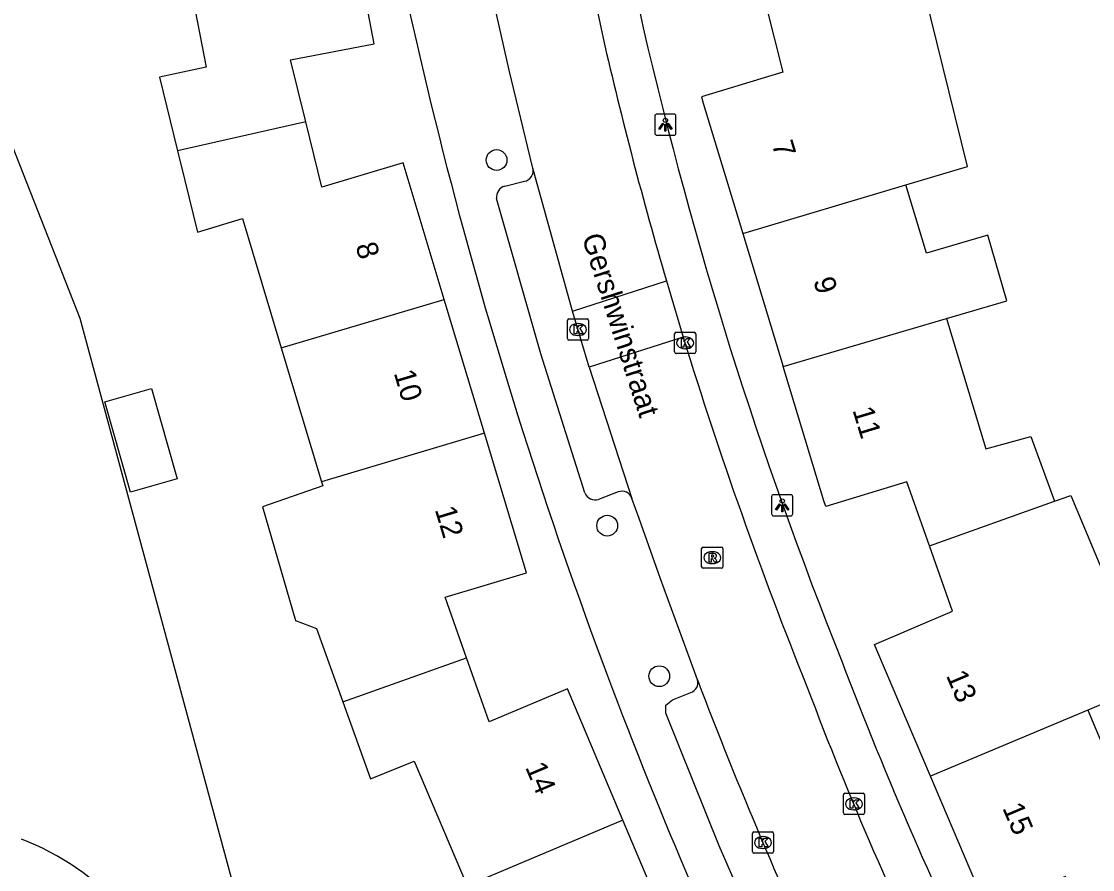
# Model space of a CAD drawing. Extents: x 159053 to 160041, y 380450 to 381422.
# Drawn here: x 159396.6 to 159447, y 380903.9 to 380943.9 of the extents above; entities that cross this region are included whole.
import ezdxf

# ---------------------------------------------------------------- set-up
doc = ezdxf.new("R2010")
doc.units = 0
for name, color, linetype in [('IMGEO_Boom', 7, 'Continuous'), ('IMGEO_Groenvoorziening', 7, 'Continuous'), ('IMGEO_Kolk', 7, 'Continuous'), ('IMGEO_Lichtpunt', 7, 'Continuous'), ('IMGEO_Openbare_ruimte_label', 7, 'Continuous'), ('IMGEO_Pand', 7, 'Continuous'), ('IMGEO_Pand_nummerreeks', 7, 'Continuous'), ('IMGEO_Rijbaan_lokaal_open', 7, 'Continuous'), ('IMGEO_Rioolput', 7, 'Continuous'), ('IMGEO_Voetpad_gesloten', 7, 'Continuous'), ('IMGEO_Voetpad_open', 7, 'Continuous')]:
    doc.layers.add(name, color=color, linetype=linetype)

msp = doc.modelspace()

# ---------------------------------------------------------------- linework, layer by layer
at = {"layer": 'IMGEO_Boom'}
for centre in [(159418.941, 380937.333), (159424.152, 380920.106), (159426.603, 380913.013)]:
    msp.add_circle(centre, 0.489, dxfattribs=at)
at = {"layer": 'IMGEO_Groenvoorziening'}
msp.add_lwpolyline([(159387.783, 380959.221), (159399.303, 380929.877), (159412.172, 380882.306), (159415.898, 380867.448), (159416.608, 380864.597)], dxfattribs=at)
at = {"layer": 'IMGEO_Kolk'}
for p, q in [((159422.349, 380929.845), (159423.201, 380929.845)), ((159422.274, 380928.919), (159422.274, 380929.771)), ((159422.762, 380929.625), (159422.787, 380929.625)), ((159423.275, 380929.771), (159423.275, 380928.919)), ((159423.201, 380928.845), (159422.349, 380928.845)), ((159422.785, 380929.065), (159422.76, 380929.065)), ((159427.322, 380928.292), (159427.322, 380929.144)), ((159427.397, 380929.218), (159428.249, 380929.218)), ((159427.81, 380928.998), (159427.835, 380928.998)), ((159428.323, 380929.144), (159428.323, 380928.292)), ((159427.833, 380928.438), (159427.808, 380928.438)), ((159428.249, 380928.218), (159427.397, 380928.218)), ((159435.274, 380906.567), (159435.274, 380907.419)), ((159435.349, 380907.493), (159436.201, 380907.493)), ((159435.762, 380907.273), (159435.787, 380907.273)), ((159436.275, 380907.419), (159436.275, 380906.567)), ((159435.785, 380906.713), (159435.76, 380906.713)), ((159436.201, 380906.493), (159435.349, 380906.493)), ((159430.988, 380904.746), (159430.988, 380905.598)), ((159431.063, 380905.672), (159431.915, 380905.672)), ((159431.989, 380905.598), (159431.989, 380904.746)), ((159431.476, 380905.452), (159431.501, 380905.452)), ((159431.915, 380904.672), (159431.063, 380904.672)), ((159431.499, 380904.892), (159431.474, 380904.892))]:
    msp.add_line(p, q, dxfattribs=at)
for points in [[(159422.349, 380929.845), (159423.201, 380929.845)], [(159422.274, 380928.919), (159422.274, 380929.771)], [(159422.595, 380929.545), (159422.718, 380929.545), (159422.718, 380929.394), (159422.848, 380929.545), (159423.012, 380929.545), (159422.866, 380929.394), (159423.019, 380929.145), (159422.867, 380929.145), (159422.782, 380929.309), (159422.718, 380929.242), (159422.718, 380929.145), (159422.595, 380929.145), (159422.595, 380929.545)], [(159423.275, 380929.771), (159423.275, 380928.919)], [(159423.201, 380928.845), (159422.349, 380928.845)], [(159427.322, 380928.292), (159427.322, 380929.144)], [(159427.397, 380929.218), (159428.249, 380929.218)], [(159427.643, 380928.918), (159427.766, 380928.918), (159427.766, 380928.767), (159427.896, 380928.918), (159428.06, 380928.918), (159427.914, 380928.767), (159428.067, 380928.518), (159427.915, 380928.518), (159427.83, 380928.682), (159427.766, 380928.615), (159427.766, 380928.518), (159427.643, 380928.518), (159427.643, 380928.918)], [(159428.323, 380929.144), (159428.323, 380928.292)], [(159428.249, 380928.218), (159427.397, 380928.218)], [(159435.274, 380906.567), (159435.274, 380907.419)], [(159435.349, 380907.493), (159436.201, 380907.493)], [(159435.595, 380907.193), (159435.718, 380907.193), (159435.718, 380907.042), (159435.848, 380907.193), (159436.012, 380907.193), (159435.866, 380907.042), (159436.019, 380906.793), (159435.867, 380906.793), (159435.782, 380906.957), (159435.718, 380906.89), (159435.718, 380906.793), (159435.595, 380906.793), (159435.595, 380907.193)], [(159436.275, 380907.419), (159436.275, 380906.567)], [(159436.201, 380906.493), (159435.349, 380906.493)], [(159430.988, 380904.746), (159430.988, 380905.598)], [(159431.063, 380905.672), (159431.915, 380905.672)], [(159431.989, 380905.598), (159431.989, 380904.746)], [(159431.309, 380905.372), (159431.432, 380905.372), (159431.432, 380905.221), (159431.562, 380905.372), (159431.726, 380905.372), (159431.58, 380905.221), (159431.733, 380904.972), (159431.581, 380904.972), (159431.496, 380905.136), (159431.432, 380905.069), (159431.432, 380904.972), (159431.309, 380904.972), (159431.309, 380905.372)], [(159431.915, 380904.672), (159431.063, 380904.672)]]:
    msp.add_lwpolyline(points, dxfattribs=at)
for centre, start, end in [((159422.351, 380929.769), 91.552, 178.448), ((159422.351, 380929.769), 91.552, 178.448), ((159423.199, 380929.769), 1.552, 88.448), ((159423.199, 380929.769), 1.552, 88.448), ((159422.351, 380928.921), 181.552, 268.448), ((159422.351, 380928.921), 181.552, 268.448), ((159423.199, 380928.921), 271.552, 358.448), ((159423.199, 380928.921), 271.552, 358.448), ((159427.399, 380929.142), 91.552, 178.448), ((159427.399, 380929.142), 91.552, 178.448), ((159428.247, 380929.142), 1.552, 88.448), ((159428.247, 380929.142), 1.552, 88.448), ((159427.399, 380928.294), 181.552, 268.448), ((159427.399, 380928.294), 181.552, 268.448), ((159428.247, 380928.294), 271.552, 358.448), ((159428.247, 380928.294), 271.552, 358.448), ((159435.351, 380907.417), 91.552, 178.448), ((159435.351, 380907.417), 91.552, 178.448), ((159436.199, 380907.417), 1.552, 88.448), ((159436.199, 380907.417), 1.552, 88.448), ((159435.351, 380906.569), 181.552, 268.448), ((159435.351, 380906.569), 181.552, 268.448), ((159436.199, 380906.569), 271.552, 358.448), ((159436.199, 380906.569), 271.552, 358.448), ((159431.065, 380905.596), 91.552, 178.448), ((159431.065, 380905.596), 91.552, 178.448), ((159431.913, 380905.596), 1.552, 88.448), ((159431.913, 380905.596), 1.552, 88.448), ((159431.065, 380904.748), 181.552, 268.448), ((159431.065, 380904.748), 181.552, 268.448), ((159431.913, 380904.748), 271.552, 358.448), ((159431.913, 380904.748), 271.552, 358.448)]:
    msp.add_arc(centre, 0.0765, start, end, dxfattribs=at)
for centre, major_axis, ratio, start_param, end_param in [((159422.761, 380929.345), (-0.387, 0.002), 0.722429, 4.712389, 7.853982), ((159422.786, 380929.345), (-0.39, 0.002), 0.717154, 1.570796, 4.712389), ((159427.809, 380928.718), (-0.387, 0.002), 0.722429, 4.712389, 7.853982), ((159427.834, 380928.718), (-0.39, 0.002), 0.717154, 1.570796, 4.712389), ((159435.761, 380906.993), (-0.387, 0.002), 0.722429, 4.712389, 7.853982), ((159435.786, 380906.993), (-0.39, 0.002), 0.717154, 1.570796, 4.712389), ((159431.475, 380905.172), (-0.387, 0.002), 0.722429, 4.712389, 7.853982), ((159431.5, 380905.172), (-0.39, 0.002), 0.717154, 1.570796, 4.712389)]:
    msp.add_ellipse(centre, major_axis=major_axis, ratio=ratio, start_param=start_param, end_param=end_param, dxfattribs=at)
at = {"layer": 'IMGEO_Lichtpunt'}
for p, q in [((159426.393, 380939.404), (159426.393, 380938.597)), ((159426.393, 380939.404), (159426.393, 380938.597)), ((159427.295, 380939.499), (159426.487, 380939.499)), ((159427.295, 380939.499), (159426.487, 380939.499)), ((159427.389, 380938.597), (159427.389, 380939.404)), ((159427.389, 380938.597), (159427.389, 380939.404)), ((159426.487, 380938.503), (159427.295, 380938.503)), ((159426.487, 380938.503), (159427.295, 380938.503)), ((159431.897, 380921.468), (159431.897, 380920.661)), ((159431.897, 380921.468), (159431.897, 380920.661)), ((159432.799, 380921.563), (159431.991, 380921.563)), ((159432.799, 380921.563), (159431.991, 380921.563)), ((159432.893, 380920.661), (159432.893, 380921.468)), ((159432.893, 380920.661), (159432.893, 380921.468)), ((159431.991, 380920.567), (159432.799, 380920.567)), ((159431.991, 380920.567), (159432.799, 380920.567))]:
    msp.add_line(p, q, dxfattribs=at)
for points in [[(159426.767, 380939.068), (159426.806, 380939.04), (159426.618, 380938.778), (159426.58, 380938.805), (159426.767, 380939.068)], [(159426.869, 380939.02), (159426.916, 380939.02), (159426.916, 380938.698), (159426.869, 380938.698), (159426.869, 380939.02)], [(159426.979, 380939.04), (159427.017, 380939.067), (159427.204, 380938.805), (159427.165, 380938.777), (159426.979, 380939.04)], [(159432.271, 380921.132), (159432.31, 380921.104), (159432.122, 380920.842), (159432.084, 380920.869), (159432.271, 380921.132)], [(159432.373, 380921.084), (159432.42, 380921.084), (159432.42, 380920.762), (159432.373, 380920.762), (159432.373, 380921.084)], [(159432.483, 380921.104), (159432.521, 380921.131), (159432.708, 380920.869), (159432.669, 380920.841), (159432.483, 380921.104)]]:
    msp.add_lwpolyline(points, dxfattribs=at)
for centre in [(159426.892, 380939.202), (159432.396, 380921.266)]:
    msp.add_circle(centre, 0.0994, dxfattribs=at)
for centre, start, end in [((159426.487, 380939.404), 90, 180), ((159426.487, 380939.404), 90, 180), ((159427.295, 380939.404), 0, 90), ((159427.295, 380939.404), 0, 90), ((159426.487, 380938.597), 180, 270), ((159426.487, 380938.597), 180, 270), ((159427.295, 380938.597), 270, 0), ((159427.295, 380938.597), 270, 360), ((159431.991, 380921.468), 90, 180), ((159431.991, 380921.468), 90, 180), ((159432.799, 380921.468), 0, 90), ((159432.799, 380921.468), 0, 90), ((159431.991, 380920.661), 180, 270), ((159431.991, 380920.661), 180, 270), ((159432.799, 380920.661), 270, 0), ((159432.799, 380920.661), 270, 360)]:
    msp.add_arc(centre, 0.0946, start, end, dxfattribs=at)
at = {"layer": 'IMGEO_Pand'}
for points in [[(159409.953, 380939.13), (159409.24, 380942.056), (159413.168, 380942.808), (159411.879, 380949.539)], [(159404.022, 380948.11), (159405.255, 380941.709), (159403.062, 380941.231), (159403.913, 380937.763)], [(159438.223, 380936.165), (159441.124, 380937.032), (159438.82, 380946.412)], [(159431.627, 380944.647), (159432.417, 380941.468), (159428.589, 380940.306), (159428.676, 380940.019), (159430.541, 380933.871)], [(159409.953, 380939.13), (159403.913, 380937.763)], [(159416.47, 380930.766), (159414.534, 380937.199), (159410.704, 380936.047), (159409.953, 380939.13)], [(159403.913, 380937.763), (159404.254, 380936.376), (159404.853, 380933.938), (159406.964, 380934.576), (159408.796, 380928.486)], [(159430.541, 380933.871), (159438.223, 380936.165)], [(159440.128, 380929.86), (159442.983, 380930.698), (159442.075, 380933.79), (159439.196, 380932.945), (159438.223, 380936.165)], [(159430.541, 380933.871), (159432.442, 380927.604)], [(159408.796, 380928.486), (159416.47, 380930.766)], [(159418.369, 380924.458), (159416.47, 380930.766)], [(159432.442, 380927.604), (159440.128, 380929.86)], [(159440.128, 380929.86), (159441.982, 380923.725), (159444.104, 380924.312), (159445.222, 380921.253)], [(159408.796, 380928.486), (159410.696, 380922.171)], [(159439.335, 380919.157), (159438.27, 380922.174), (159434.442, 380921.012), (159434.361, 380921.28), (159432.442, 380927.604)], [(159401.699, 380921.678), (159400.484, 380925.933), (159402.685, 380926.562), (159403.9, 380922.307), (159401.699, 380921.678)], [(159418.369, 380924.458), (159410.696, 380922.171)], [(159417.526, 380913.88), (159416.517, 380916.735), (159420.347, 380917.887), (159418.369, 380924.458)], [(159410.696, 380922.171), (159410.751, 380921.987), (159407.916, 380920.993), (159409.474, 380915.644), (159410.451, 380915.26), (159411.697, 380911.8)], [(159439.335, 380919.157), (159445.222, 380921.253)], [(159445.222, 380921.253), (159445.993, 380921.527), (159449.718, 380912.643), (159446.793, 380911.415)], [(159439.379, 380908.299), (159436.855, 380914.238), (159436.742, 380914.504), (159440.424, 380916.069), (159439.335, 380919.157)], [(159411.697, 380911.8), (159417.526, 380913.88)], [(159424.886, 380906.225), (159422.277, 380912.418), (159418.591, 380910.865), (159417.526, 380913.88)], [(159411.697, 380911.8), (159413.002, 380908.175), (159415.055, 380909.013), (159417.551, 380903.138)], [(159446.793, 380911.415), (159449.265, 380905.517), (159451.363, 380906.349), (159452.697, 380903.191), (159451.578, 380902.697), (159448.411, 380901.353), (159446.975, 380900.743), (159445.736, 380903.567), (159442.047, 380902.022), (159439.379, 380908.299)], [(159446.793, 380911.415), (159439.379, 380908.299)], [(159424.886, 380906.225), (159417.551, 380903.138)], [(159427.441, 380900.163), (159424.886, 380906.225)]]:
    msp.add_lwpolyline(points, dxfattribs=at)
at = {"layer": 'IMGEO_Rijbaan_lokaal_open'}
for points in [[(159419.726, 380964.951), (159421.546, 380954.773), (159422.519, 380949.866), (159423.957, 380943.077)], [(159420.654, 380936.951), (159420.406, 380937.922), (159419.538, 380941.564), (159418.584, 380945.758)], [(159422.516, 380930.212), (159420.654, 380936.951)], [(159422.516, 380930.212), (159426.938, 380931.641)], [(159426.938, 380931.641), (159427.732, 380928.985)], [(159423.308, 380927.58), (159422.516, 380930.212)], [(159427.732, 380928.985), (159423.308, 380927.58)], [(159423.308, 380927.58), (159425.318, 380921.388)], [(159428.405, 380912.844), (159428.036, 380913.828), (159426.667, 380917.593), (159425.651, 380920.437), (159425.318, 380921.388)]]:
    msp.add_lwpolyline(points, dxfattribs=at)
for centre, radius, start, end in [((159626.14, 380989.673), 207.483, 192.97807, 196.24206), ((159625.145, 380989.617), 206.514, 197.07339, 201.94113), ((159618.579, 380984.756), 203.316, 200.71342, 205.2654), ((159585.371, 380969.529), 162.159, 200.60872, 206.46344)]:
    msp.add_arc(centre, radius, start, end, dxfattribs=at)
at = {"layer": 'IMGEO_Rioolput'}
for p, q in [((159428.6, 380918.171), (159428.6, 380919.023)), ((159428.675, 380919.097), (159429.527, 380919.097)), ((159429.088, 380918.877), (159429.113, 380918.877)), ((159429.601, 380919.023), (159429.601, 380918.171)), ((159429.111, 380918.317), (159429.086, 380918.317)), ((159429.527, 380918.097), (159428.675, 380918.097))]:
    msp.add_line(p, q, dxfattribs=at)
for points in [[(159428.6, 380918.171), (159428.6, 380919.023)], [(159428.675, 380919.097), (159429.527, 380919.097)], [(159429.189, 380918.795), (159428.937, 380918.797), (159428.937, 380918.397)], [(159429.115, 380918.716), (159429.061, 380918.716), (159429.061, 380918.635)], [(159429.601, 380919.023), (159429.601, 380918.171)], [(159428.937, 380918.397), (159429.061, 380918.397), (159429.061, 380918.559), (159429.072, 380918.559)], [(159429.061, 380918.635), (159429.113, 380918.635)], [(159429.119, 380918.53), (159429.19, 380918.397), (159429.33, 380918.397), (159429.265, 380918.523)], [(159429.527, 380918.097), (159428.675, 380918.097)]]:
    msp.add_lwpolyline(points, dxfattribs=at)
for centre, radius, start, end in [((159428.677, 380919.021), 0.0765, 91.552, 178.448), ((159428.677, 380919.021), 0.0765, 91.552, 178.448), ((159429.121, 380918.62), 0.0964, 77.0061, 93.1865), ((159429.135, 380918.677), 0.0378, 276.6634, 79.6772), ((159429.188, 380918.685), 0.109, 350.3612, 89.416), ((159429.525, 380919.021), 0.0765, 1.552, 88.448), ((159429.525, 380919.021), 0.0765, 1.552, 88.448), ((159429.071, 380918.506), 0.0533, 26.0293, 88.6989), ((159429.097, 380918.824), 0.19, 274.7715, 282.9687), ((159429.186, 380918.685), 0.112, 277.5842, 350.9817), ((159429.17, 380918.47), 0.108, 29.5134, 73.7905), ((159428.677, 380918.173), 0.0765, 181.552, 268.448), ((159428.677, 380918.173), 0.0765, 181.552, 268.448), ((159429.525, 380918.173), 0.0765, 271.552, 358.448), ((159429.525, 380918.173), 0.0765, 271.552, 358.448)]:
    msp.add_arc(centre, radius, start, end, dxfattribs=at)
for centre, major_axis, ratio, start_param, end_param in [((159429.087, 380918.597), (-0.387, 0.002), 0.722429, 4.712389, 7.853982), ((159429.112, 380918.597), (-0.39, 0.002), 0.717154, 1.570796, 4.712389)]:
    msp.add_ellipse(centre, major_axis=major_axis, ratio=ratio, start_param=start_param, end_param=end_param, dxfattribs=at)
at = {"layer": 'IMGEO_Voetpad_gesloten'}
msp.add_arc((159392.297, 380894.073), 12.034, 13.7517, 69.2683, dxfattribs=at)
at = {"layer": 'IMGEO_Voetpad_open'}
for points in [[(159419.329, 380936.105), (159420.257, 380936.332)], [(159423.101, 380921.648), (159421.017, 380928.2), (159418.94, 380935.516)], [(159424.665, 380921.693), (159423.745, 380921.345)], [(159432.485, 380898.002), (159429.428, 380905.026), (159426.906, 380911.269), (159426.92, 380911.65), (159427.22, 380911.895), (159428.084, 380912.239)]]:
    msp.add_lwpolyline(points, dxfattribs=at)
for centre, radius, start, end in [((159643.326, 380995.404), 234.129, 188.67315, 200.59863), ((159680.029, 381001.49), 260.697, 190.15695, 192.83868), ((159624.348, 380989.377), 203.718, 192.99702, 201.80088), ((159420.167, 380936.827), 0.503, 280.3152, 14.3361), ((159419.471, 380935.588), 0.536, 105.3424, 187.7728), ((159424.847, 380921.231), 0.496, 18.4115, 111.5163), ((159423.597, 380921.866), 0.542, 203.7324, 285.8739), ((159607.884, 380979.275), 184.709, 200.78794, 206.29061), ((159654.06, 380999.595), 245.652, 200.63276, 205.61432), ((159427.936, 380912.705), 0.489, 287.6372, 16.4639)]:
    msp.add_arc(centre, radius, start, end, dxfattribs=at)

# ---------------------------------------------------------------- texts
at = {"layer": 'IMGEO_Openbare_ruimte_label'}
msp.add_text('Gershwinstraat', height=1, rotation=287.7643, dxfattribs=at).set_placement((159422.944, 380933.701))
at = {"layer": 'IMGEO_Pand_nummerreeks'}
for s, rotation, p in [('7', 286.8734, (159431.897, 380938.085)), ('8', 286.752, (159412.284, 380933.294)), ('9', 286.8734, (159433.848, 380931.654)), ('10', 286.752, (159414.089, 380927.299)), ('11', 286.8756, (159435.698, 380925.555)), ('12', 286.752, (159416.024, 380920.868)), ('13', 293.0261, (159440.1, 380913.046)), ('14', 292.8491, (159420.275, 380908.725)), ('15', 293.0261, (159442.753, 380906.805))]:
    msp.add_text(s, height=1, rotation=rotation, dxfattribs=at).set_placement(p)

doc.saveas('drawing.dxf')
